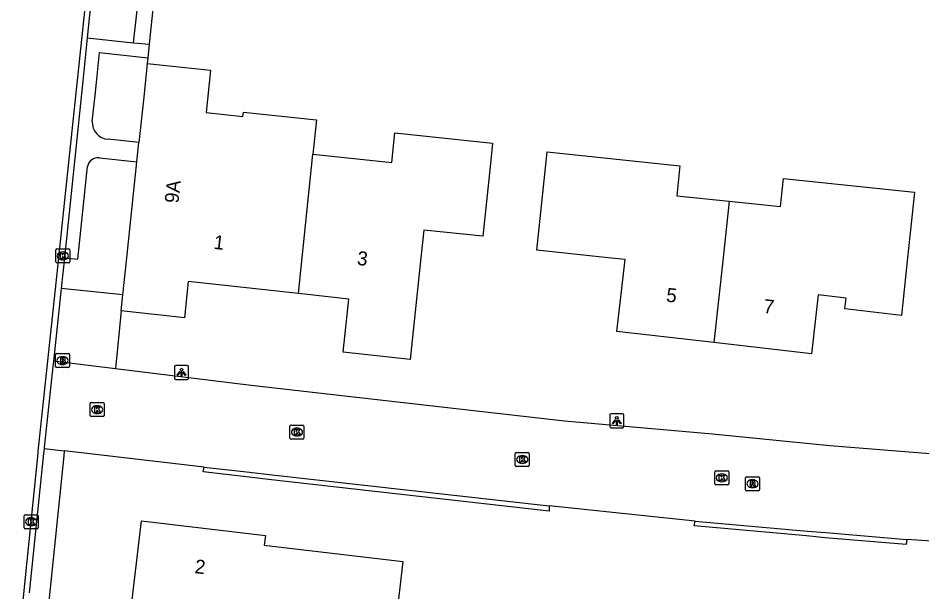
# Model space of a CAD drawing. Extents: x 162157 to 163165, y 378998 to 380775.
# Drawn here: x 162286.7 to 162351.3, y 380476.1 to 380517.1 of the extents above; entities that cross this region are included whole.
import ezdxf

# ---------------------------------------------------------------- set-up
doc = ezdxf.new("R2010")
doc.units = 0
for name, color, linetype in [('IMGEO_Brandkraan', 7, 'Continuous'), ('IMGEO_Groenvoorziening', 7, 'Continuous'), ('IMGEO_Kolk', 7, 'Continuous'), ('IMGEO_Lichtpunt', 7, 'Continuous'), ('IMGEO_Pand', 7, 'Continuous'), ('IMGEO_Pand_nummerreeks', 7, 'Continuous'), ('IMGEO_Rijbaan_lokaal_gesloten', 7, 'Continuous'), ('IMGEO_Rijbaan_lokaal_open', 7, 'Continuous'), ('IMGEO_Rioolput', 7, 'Continuous'), ('IMGEO_Voetpad_open', 7, 'Continuous')]:
    doc.layers.add(name, color=color, linetype=linetype)

msp = doc.modelspace()

# ---------------------------------------------------------------- linework, layer by layer
at = {"layer": 'IMGEO_Brandkraan'}
for p, q in [((162289.358, 380492.22), (162289.358, 380493.072)), ((162289.433, 380493.146), (162290.285, 380493.146)), ((162289.846, 380492.926), (162289.871, 380492.926)), ((162290.359, 380493.072), (162290.359, 380492.22)), ((162290.285, 380492.146), (162289.433, 380492.146)), ((162289.869, 380492.366), (162289.844, 380492.366))]:
    msp.add_line(p, q, dxfattribs=at)
for points in [[(162289.358, 380492.22), (162289.358, 380493.072)], [(162289.433, 380493.146), (162290.285, 380493.146)], [(162289.706, 380492.846), (162289.706, 380492.446), (162289.919, 380492.446)], [(162289.937, 380492.846), (162289.706, 380492.846)], [(162289.885, 380492.765), (162289.831, 380492.765), (162289.831, 380492.689)], [(162290.359, 380493.072), (162290.359, 380492.22)], [(162290.285, 380492.146), (162289.433, 380492.146)], [(162289.831, 380492.689), (162289.884, 380492.689)], [(162289.893, 380492.613), (162289.831, 380492.613), (162289.831, 380492.532)], [(162289.831, 380492.532), (162289.893, 380492.532)]]:
    msp.add_lwpolyline(points, dxfattribs=at)
for centre, radius, start, end in [((162289.435, 380493.07), 0.0765, 91.55205, 178.44795), ((162289.435, 380493.07), 0.0765, 91.55205, 178.44795), ((162289.886, 380492.727), 0.0379, 267.82845, 90.93552), ((162289.941, 380492.701), 0.145, 59.4692, 91.53667), ((162289.966, 380492.748), 0.0922, 285.51372, 58.15012), ((162290.283, 380493.07), 0.0765, 1.55205, 88.44795), ((162290.283, 380493.07), 0.0765, 1.55205, 88.44795), ((162289.435, 380492.222), 0.0765, 181.55205, 268.44795), ((162289.435, 380492.222), 0.0765, 181.55205, 268.44795), ((162289.894, 380492.572), 0.0404, 269.87594, 90.50774), ((162289.925, 380492.697), 0.251, 268.66757, 293.53466), ((162289.971, 380492.556), 0.105, 301.31148, 78.98903), ((162290.283, 380492.222), 0.0765, 271.55205, 358.44795), ((162290.283, 380492.222), 0.0765, 271.55205, 358.44795)]:
    msp.add_arc(centre, radius, start, end, dxfattribs=at)
for centre, major_axis, ratio, start_param, end_param in [((162289.845, 380492.646), (-0.387, 0.002), 0.722429, 4.712389, 7.853982), ((162289.87, 380492.646), (-0.39, 0.002), 0.717154, 1.570796, 4.712389)]:
    msp.add_ellipse(centre, major_axis=major_axis, ratio=ratio, start_param=start_param, end_param=end_param, dxfattribs=at)
at = {"layer": 'IMGEO_Groenvoorziening'}
for points in [[(162294.943, 380515.381), (162295.812, 380523.22), (162296.858, 380523.1)], [(162296.858, 380523.1), (162296.058, 380515.267)], [(162295.96, 380514.309), (162295.919, 380513.902)], [(162294.171, 380497.345), (162289.765, 380497.81)], [(162294.051, 380496.207), (162293.677, 380492.313), (162293.655, 380492.079)], [(162324.65, 380482.251), (162324.663, 380481.872), (162304.6, 380484.15), (162303.2, 380484.309), (162299.911, 380484.683), (162299.977, 380485.03)], [(162350.248, 380479.858), (162350.201, 380479.49), (162344.4, 380479.965), (162343.071, 380480.109), (162335.038, 380480.824), (162335.095, 380481.17)]]:
    msp.add_lwpolyline(points, dxfattribs=at)
at = {"layer": 'IMGEO_Kolk'}
for p, q in [((162289.382, 380499.707), (162289.382, 380500.559)), ((162289.457, 380500.633), (162290.309, 380500.633)), ((162290.383, 380500.559), (162290.383, 380499.707)), ((162289.893, 380499.853), (162289.868, 380499.853)), ((162289.87, 380500.413), (162289.895, 380500.413)), ((162290.309, 380499.633), (162289.457, 380499.633)), ((162291.838, 380488.714), (162291.838, 380489.566)), ((162291.913, 380489.64), (162292.765, 380489.64)), ((162292.839, 380489.566), (162292.839, 380488.714)), ((162292.326, 380489.42), (162292.351, 380489.42)), ((162292.765, 380488.64), (162291.913, 380488.64)), ((162292.349, 380488.86), (162292.324, 380488.86)), ((162306.123, 380487.108), (162306.123, 380487.96)), ((162306.198, 380488.034), (162307.05, 380488.034)), ((162306.611, 380487.814), (162306.636, 380487.814)), ((162307.124, 380487.96), (162307.124, 380487.108)), ((162307.05, 380487.034), (162306.198, 380487.034)), ((162306.634, 380487.254), (162306.609, 380487.254)), ((162322.235, 380485.15), (162322.235, 380486.002)), ((162322.31, 380486.076), (162323.162, 380486.076)), ((162322.723, 380485.856), (162322.748, 380485.856)), ((162323.236, 380486.002), (162323.236, 380485.15)), ((162323.162, 380485.076), (162322.31, 380485.076)), ((162322.746, 380485.296), (162322.721, 380485.296)), ((162336.506, 380483.835), (162336.506, 380484.687)), ((162336.581, 380484.761), (162337.433, 380484.761)), ((162336.994, 380484.541), (162337.019, 380484.541)), ((162337.507, 380484.687), (162337.507, 380483.835)), ((162337.433, 380483.761), (162336.581, 380483.761)), ((162337.017, 380483.981), (162336.992, 380483.981)), ((162287.115, 380480.696), (162287.115, 380481.548)), ((162287.19, 380481.622), (162288.042, 380481.622)), ((162287.603, 380481.402), (162287.628, 380481.402)), ((162288.116, 380481.548), (162288.116, 380480.696)), ((162288.042, 380480.622), (162287.19, 380480.622)), ((162287.626, 380480.842), (162287.601, 380480.842))]:
    msp.add_line(p, q, dxfattribs=at)
for points in [[(162289.382, 380499.707), (162289.382, 380500.559)], [(162289.457, 380500.633), (162290.309, 380500.633)], [(162290.383, 380500.559), (162290.383, 380499.707)], [(162289.703, 380500.333), (162289.826, 380500.333), (162289.826, 380500.182), (162289.956, 380500.333), (162290.12, 380500.333), (162289.974, 380500.182), (162290.127, 380499.933), (162289.975, 380499.933), (162289.89, 380500.097), (162289.826, 380500.03), (162289.826, 380499.933), (162289.703, 380499.933), (162289.703, 380500.333)], [(162290.309, 380499.633), (162289.457, 380499.633)], [(162291.838, 380488.714), (162291.838, 380489.566)], [(162291.913, 380489.64), (162292.765, 380489.64)], [(162292.839, 380489.566), (162292.839, 380488.714)], [(162292.159, 380489.34), (162292.282, 380489.34), (162292.282, 380489.189), (162292.412, 380489.34), (162292.576, 380489.34), (162292.43, 380489.189), (162292.583, 380488.94), (162292.431, 380488.94), (162292.346, 380489.104), (162292.282, 380489.037), (162292.282, 380488.94), (162292.159, 380488.94), (162292.159, 380489.34)], [(162292.765, 380488.64), (162291.913, 380488.64)], [(162306.123, 380487.108), (162306.123, 380487.96)], [(162306.198, 380488.034), (162307.05, 380488.034)], [(162306.444, 380487.734), (162306.567, 380487.734), (162306.567, 380487.583), (162306.697, 380487.734), (162306.861, 380487.734), (162306.715, 380487.583), (162306.868, 380487.334), (162306.716, 380487.334), (162306.631, 380487.498), (162306.567, 380487.431), (162306.567, 380487.334), (162306.444, 380487.334), (162306.444, 380487.734)], [(162307.124, 380487.96), (162307.124, 380487.108)], [(162307.05, 380487.034), (162306.198, 380487.034)], [(162322.235, 380485.15), (162322.235, 380486.002)], [(162322.31, 380486.076), (162323.162, 380486.076)], [(162322.556, 380485.776), (162322.679, 380485.776), (162322.679, 380485.625), (162322.809, 380485.776), (162322.973, 380485.776), (162322.827, 380485.625), (162322.98, 380485.376), (162322.828, 380485.376), (162322.743, 380485.54), (162322.679, 380485.473), (162322.679, 380485.376), (162322.556, 380485.376), (162322.556, 380485.776)], [(162323.236, 380486.002), (162323.236, 380485.15)], [(162323.162, 380485.076), (162322.31, 380485.076)], [(162336.506, 380483.835), (162336.506, 380484.687)], [(162336.581, 380484.761), (162337.433, 380484.761)], [(162336.827, 380484.461), (162336.95, 380484.461), (162336.95, 380484.31), (162337.08, 380484.461), (162337.244, 380484.461), (162337.098, 380484.31), (162337.251, 380484.061), (162337.099, 380484.061), (162337.014, 380484.225), (162336.95, 380484.158), (162336.95, 380484.061), (162336.827, 380484.061), (162336.827, 380484.461)], [(162337.507, 380484.687), (162337.507, 380483.835)], [(162337.433, 380483.761), (162336.581, 380483.761)], [(162287.115, 380480.696), (162287.115, 380481.548)], [(162287.19, 380481.622), (162288.042, 380481.622)], [(162287.436, 380481.322), (162287.559, 380481.322), (162287.559, 380481.171), (162287.689, 380481.322), (162287.853, 380481.322), (162287.707, 380481.171), (162287.86, 380480.922), (162287.708, 380480.922), (162287.623, 380481.086), (162287.559, 380481.019), (162287.559, 380480.922), (162287.436, 380480.922), (162287.436, 380481.322)], [(162288.116, 380481.548), (162288.116, 380480.696)], [(162288.042, 380480.622), (162287.19, 380480.622)]]:
    msp.add_lwpolyline(points, dxfattribs=at)
for centre, start, end in [((162289.459, 380500.557), 91.55205, 178.44795), ((162289.459, 380500.557), 91.55205, 178.44795), ((162290.307, 380500.557), 1.55205, 88.44795), ((162290.307, 380500.557), 1.55205, 88.44795), ((162289.459, 380499.709), 181.55205, 268.44795), ((162289.459, 380499.709), 181.55205, 268.44795), ((162290.307, 380499.709), 271.55205, 358.44795), ((162290.307, 380499.709), 271.55205, 358.44795), ((162291.915, 380489.564), 91.55205, 178.44795), ((162291.915, 380489.564), 91.55205, 178.44795), ((162292.763, 380489.564), 1.55205, 88.44795), ((162292.763, 380489.564), 1.55205, 88.44795), ((162291.915, 380488.716), 181.55205, 268.44795), ((162291.915, 380488.716), 181.55205, 268.44795), ((162292.763, 380488.716), 271.55205, 358.44795), ((162292.763, 380488.716), 271.55205, 358.44795), ((162306.2, 380487.958), 91.55205, 178.44795), ((162306.2, 380487.958), 91.55205, 178.44795), ((162307.048, 380487.958), 1.55205, 88.44795), ((162307.048, 380487.958), 1.55205, 88.44795), ((162306.2, 380487.11), 181.55205, 268.44795), ((162306.2, 380487.11), 181.55205, 268.44795), ((162307.048, 380487.11), 271.55205, 358.44795), ((162307.048, 380487.11), 271.55205, 358.44795), ((162322.312, 380486), 91.55205, 178.44795), ((162322.312, 380486), 91.55205, 178.44795), ((162323.16, 380486), 1.55205, 88.44795), ((162323.16, 380486), 1.55205, 88.44795), ((162322.312, 380485.152), 181.55205, 268.44795), ((162322.312, 380485.152), 181.55205, 268.44795), ((162323.16, 380485.152), 271.55205, 358.44795), ((162323.16, 380485.152), 271.55205, 358.44795), ((162336.583, 380484.685), 91.55205, 178.44795), ((162336.583, 380484.685), 91.55205, 178.44795), ((162337.431, 380484.685), 1.55205, 88.44795), ((162337.431, 380484.685), 1.55205, 88.44795), ((162336.583, 380483.837), 181.55205, 268.44795), ((162336.583, 380483.837), 181.55205, 268.44795), ((162337.431, 380483.837), 271.55205, 358.44795), ((162337.431, 380483.837), 271.55205, 358.44795), ((162287.192, 380481.546), 91.55205, 178.44795), ((162287.192, 380481.546), 91.55205, 178.44795), ((162288.04, 380481.546), 1.55205, 88.44795), ((162288.04, 380481.546), 1.55205, 88.44795), ((162287.192, 380480.698), 181.55205, 268.44795), ((162287.192, 380480.698), 181.55205, 268.44795), ((162288.04, 380480.698), 271.55205, 358.44795), ((162288.04, 380480.698), 271.55205, 358.44795)]:
    msp.add_arc(centre, 0.0765, start, end, dxfattribs=at)
for centre, major_axis, ratio, start_param, end_param in [((162289.869, 380500.133), (-0.387, 0.002), 0.722429, 4.712389, 7.853982), ((162289.894, 380500.133), (-0.39, 0.002), 0.717154, 1.570796, 4.712389), ((162292.325, 380489.14), (-0.387, 0.002), 0.722429, 4.712389, 7.853982), ((162292.35, 380489.14), (-0.39, 0.002), 0.717154, 1.570796, 4.712389), ((162306.61, 380487.534), (-0.387, 0.002), 0.722429, 4.712389, 7.853982), ((162306.635, 380487.534), (-0.39, 0.002), 0.717154, 1.570796, 4.712389), ((162322.722, 380485.576), (-0.387, 0.002), 0.722429, 4.712389, 7.853982), ((162322.747, 380485.576), (-0.39, 0.002), 0.717154, 1.570796, 4.712389), ((162336.993, 380484.261), (-0.387, 0.002), 0.722429, 4.712389, 7.853982), ((162337.018, 380484.261), (-0.39, 0.002), 0.717154, 1.570796, 4.712389), ((162287.602, 380481.122), (-0.387, 0.002), 0.722429, 4.712389, 7.853982), ((162287.627, 380481.122), (-0.39, 0.002), 0.717154, 1.570796, 4.712389)]:
    msp.add_ellipse(centre, major_axis=major_axis, ratio=ratio, start_param=start_param, end_param=end_param, dxfattribs=at)
at = {"layer": 'IMGEO_Lichtpunt'}
for p, q in [((162297.866, 380492.198), (162297.866, 380491.391)), ((162297.866, 380492.198), (162297.866, 380491.391)), ((162298.768, 380492.293), (162297.96, 380492.293)), ((162298.768, 380492.293), (162297.96, 380492.293)), ((162298.862, 380491.391), (162298.862, 380492.198)), ((162298.862, 380491.391), (162298.862, 380492.198)), ((162297.96, 380491.297), (162298.768, 380491.297)), ((162297.96, 380491.297), (162298.768, 380491.297)), ((162328.999, 380488.749), (162328.999, 380487.942)), ((162328.999, 380488.749), (162328.999, 380487.942)), ((162329.901, 380488.844), (162329.093, 380488.844)), ((162329.901, 380488.844), (162329.093, 380488.844)), ((162329.995, 380487.942), (162329.995, 380488.749)), ((162329.995, 380487.942), (162329.995, 380488.749)), ((162329.093, 380487.848), (162329.901, 380487.848)), ((162329.093, 380487.848), (162329.901, 380487.848))]:
    msp.add_line(p, q, dxfattribs=at)
for points in [[(162298.24, 380491.862), (162298.279, 380491.834), (162298.091, 380491.572), (162298.053, 380491.599), (162298.24, 380491.862)], [(162298.342, 380491.814), (162298.389, 380491.814), (162298.389, 380491.492), (162298.342, 380491.492), (162298.342, 380491.814)], [(162298.452, 380491.834), (162298.49, 380491.861), (162298.677, 380491.599), (162298.638, 380491.571), (162298.452, 380491.834)], [(162329.373, 380488.413), (162329.412, 380488.385), (162329.224, 380488.123), (162329.186, 380488.15), (162329.373, 380488.413)], [(162329.475, 380488.365), (162329.522, 380488.365), (162329.522, 380488.043), (162329.475, 380488.043), (162329.475, 380488.365)], [(162329.585, 380488.385), (162329.623, 380488.412), (162329.81, 380488.15), (162329.771, 380488.122), (162329.585, 380488.385)]]:
    msp.add_lwpolyline(points, dxfattribs=at)
for centre in [(162298.365, 380491.996), (162329.498, 380488.547)]:
    msp.add_circle(centre, 0.0994, dxfattribs=at)
for centre, start, end in [((162297.96, 380492.198), 90, 180), ((162297.96, 380492.198), 90, 180), ((162298.768, 380492.198), 0, 90), ((162298.768, 380492.198), 0, 90), ((162297.96, 380491.391), 180, 270), ((162297.96, 380491.391), 180, 270), ((162298.768, 380491.391), 270, 0), ((162298.768, 380491.391), 270, 360), ((162329.093, 380488.749), 90, 180), ((162329.093, 380488.749), 90, 180), ((162329.901, 380488.749), 0, 90), ((162329.901, 380488.749), 0, 90), ((162329.093, 380487.942), 180, 270), ((162329.093, 380487.942), 180, 270), ((162329.901, 380487.942), 270, 0), ((162329.901, 380487.942), 270, 360)]:
    msp.add_arc(centre, 0.0946, start, end, dxfattribs=at)
at = {"layer": 'IMGEO_Pand'}
for points in [[(162295.919, 380513.902), (162295.738, 380512.19), (162295.64, 380511.263), (162295.321, 380508.238)], [(162295.919, 380513.902), (162300.444, 380513.424), (162300.124, 380510.39), (162302.76, 380510.112), (162302.792, 380510.414), (162308.022, 380509.862), (162307.765, 380507.412)], [(162307.765, 380507.412), (162313.397, 380506.818), (162313.619, 380508.93), (162320.614, 380508.193), (162320.436, 380506.508), (162319.912, 380501.535), (162315.686, 380501.98), (162315.479, 380500), (162314.717, 380492.718), (162309.923, 380493.24), (162310.337, 380497.048), (162306.724, 380497.442)], [(162295.176, 380506.861), (162295.321, 380508.238)], [(162306.724, 380497.442), (162306.991, 380500), (162307.765, 380507.412)], [(162336.443, 380493.928), (162329.491, 380494.737), (162330.089, 380499.87), (162328.877, 380500), (162323.776, 380500.547), (162324.3, 380505.52), (162324.516, 380507.566), (162334.011, 380506.566), (162333.787, 380504.439), (162337.529, 380504.045)], [(162294.171, 380497.345), (162294.451, 380500), (162295.176, 380506.861)], [(162337.529, 380504.045), (162341.209, 380503.657), (162341.421, 380505.671), (162350.787, 380504.684), (162350.577, 380502.676), (162350.296, 380500), (162350.055, 380497.703), (162349.862, 380495.866), (162345.808, 380496.337), (162345.898, 380497.114), (162343.901, 380497.347), (162343.409, 380493.118), (162336.443, 380493.928)], [(162337.529, 380504.045), (162337.095, 380500), (162336.443, 380493.928)], [(162306.724, 380497.442), (162298.855, 380498.299), (162298.574, 380495.715), (162294.051, 380496.207)], [(162294.051, 380496.207), (162294.171, 380497.345)], [(162294.303, 380471.095), (162294.367, 380471.637), (162294.663, 380474.14), (162295.497, 380481.198), (162304.373, 380480.149), (162304.29, 380479.45), (162314.206, 380478.278), (162313.62, 380473.313), (162313.261, 380470.278), (162300.756, 380471.757), (162300.59, 380470.352), (162299.269, 380470.508), (162297.814, 380470.68)]]:
    msp.add_lwpolyline(points, dxfattribs=at)
at = {"layer": 'IMGEO_Rijbaan_lokaal_gesloten'}
for points in [[(162286.68, 380471.979), (162288.117, 380486.031), (162288.128, 380486.137), (162289.589, 380500), (162290.022, 380504.113), (162292.56, 380528.03)], [(162292.885, 380527.995), (162291.624, 380515.72)], [(162291.624, 380515.72), (162291.306, 380512.627), (162291.212, 380511.714), (162289.993, 380500)], [(162289.993, 380500), (162289.765, 380497.81)], [(162289.765, 380497.81), (162289.246, 380492.817), (162289.213, 380492.622)], [(162289.213, 380492.622), (162289.183, 380492.446), (162288.547, 380486.441), (162288.539, 380486.359)], [(162288.539, 380486.359), (162288.501, 380485.99), (162287.48, 380476.048)]]:
    msp.add_lwpolyline(points, dxfattribs=at)
at = {"layer": 'IMGEO_Rijbaan_lokaal_open'}
for points in [[(162289.213, 380492.622), (162290.171, 380492.505), (162293.655, 380492.079)], [(162293.655, 380492.079), (162303.34, 380490.896), (162325.756, 380488.348), (162336.339, 380487.405), (162344.723, 380486.566), (162363.222, 380485.105), (162367.902, 380484.763), (162386.483, 380483.904), (162394.448, 380483.533)], [(162288.539, 380486.359), (162289.974, 380486.192)], [(162299.977, 380485.03), (162289.974, 380486.192)], [(162299.977, 380485.03), (162303.24, 380484.662), (162304.645, 380484.504), (162324.65, 380482.251)], [(162335.095, 380481.17), (162324.65, 380482.251)], [(162335.095, 380481.17), (162343.14, 380480.443), (162344.443, 380480.343), (162350.248, 380479.858)], [(162419.523, 380476.156), (162402.779, 380476.875), (162390.293, 380477.488), (162369.755, 380478.546), (162350.248, 380479.858)]]:
    msp.add_lwpolyline(points, dxfattribs=at)
at = {"layer": 'IMGEO_Rioolput'}
for p, q in [((162338.774, 380484.341), (162339.626, 380484.341)), ((162338.699, 380483.415), (162338.699, 380484.267)), ((162339.187, 380484.121), (162339.212, 380484.121)), ((162339.7, 380484.267), (162339.7, 380483.415)), ((162339.626, 380483.341), (162338.774, 380483.341)), ((162339.21, 380483.561), (162339.185, 380483.561))]:
    msp.add_line(p, q, dxfattribs=at)
for points in [[(162338.774, 380484.341), (162339.626, 380484.341)], [(162338.699, 380483.415), (162338.699, 380484.267)], [(162339.288, 380484.039), (162339.036, 380484.041), (162339.036, 380483.641)], [(162339.036, 380483.641), (162339.16, 380483.641), (162339.16, 380483.803), (162339.171, 380483.803)], [(162339.214, 380483.96), (162339.16, 380483.96), (162339.16, 380483.879)], [(162339.16, 380483.879), (162339.212, 380483.879)], [(162339.218, 380483.774), (162339.289, 380483.641), (162339.429, 380483.641), (162339.364, 380483.767)], [(162339.7, 380484.267), (162339.7, 380483.415)], [(162339.626, 380483.341), (162338.774, 380483.341)]]:
    msp.add_lwpolyline(points, dxfattribs=at)
for centre, radius, start, end in [((162338.776, 380484.265), 0.0765, 91.55205, 178.44795), ((162338.776, 380484.265), 0.0765, 91.55205, 178.44795), ((162339.624, 380484.265), 0.0765, 1.55205, 88.44795), ((162339.624, 380484.265), 0.0765, 1.55205, 88.44795), ((162339.17, 380483.75), 0.0533, 26.02933, 88.69889), ((162339.196, 380484.068), 0.19, 274.7715, 282.96867), ((162339.22, 380483.864), 0.0964, 77.00612, 93.18647), ((162339.234, 380483.921), 0.0378, 276.66336, 79.67722), ((162339.287, 380483.929), 0.109, 350.36119, 89.41601), ((162339.285, 380483.929), 0.112, 277.58423, 350.98172), ((162339.269, 380483.714), 0.108, 29.51342, 73.79051), ((162338.776, 380483.417), 0.0765, 181.55205, 268.44795), ((162338.776, 380483.417), 0.0765, 181.55205, 268.44795), ((162339.624, 380483.417), 0.0765, 271.55205, 358.44795), ((162339.624, 380483.417), 0.0765, 271.55205, 358.44795)]:
    msp.add_arc(centre, radius, start, end, dxfattribs=at)
for centre, major_axis, ratio, start_param, end_param in [((162339.186, 380483.841), (-0.387, 0.002), 0.722429, 4.712389, 7.853982), ((162339.211, 380483.841), (-0.39, 0.002), 0.717154, 1.570796, 4.712389)]:
    msp.add_ellipse(centre, major_axis=major_axis, ratio=ratio, start_param=start_param, end_param=end_param, dxfattribs=at)
at = {"layer": 'IMGEO_Voetpad_open'}
for points in [[(162291.624, 380515.72), (162294.943, 380515.381)], [(162294.943, 380515.381), (162296.058, 380515.267)], [(162296.058, 380515.267), (162295.96, 380514.309)], [(162291.986, 380509.752), (162292.182, 380511.615), (162292.279, 380512.531), (162292.504, 380514.673), (162295.96, 380514.309)], [(162295.321, 380508.238), (162293.114, 380508.47)], [(162292.498, 380507.144), (162295.176, 380506.861)], [(162289.993, 380500), (162290.947, 380499.899), (162291.644, 380506.52)], [(162289.974, 380486.192), (162289.959, 380485.832), (162288.488, 380471.745)]]:
    msp.add_lwpolyline(points, dxfattribs=at)
for centre, radius, start, end in [((162293.207, 380509.689), 1.222, 177.03223, 265.65526), ((162292.392, 380506.393), 0.759, 81.97778, 170.33186)]:
    msp.add_arc(centre, radius, start, end, dxfattribs=at)

# ---------------------------------------------------------------- texts
at = {"layer": 'IMGEO_Pand_nummerreeks'}
for s, rotation, p in [('9A', 83.96124, (162298.147, 380503.869)), ('1', 353.78341, (162300.636, 380500.64)), ('3', 353.40341, (162310.887, 380499.498)), ('5', 353.36494, (162332.988, 380496.867)), ('7', 353.36515, (162339.947, 380496.057)), ('2', 353.26202, (162299.274, 380477.45))]:
    msp.add_text(s, height=1, rotation=rotation, dxfattribs=at).set_placement(p)

doc.saveas('drawing.dxf')
